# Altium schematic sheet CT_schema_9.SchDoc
size 226 x 144 mm
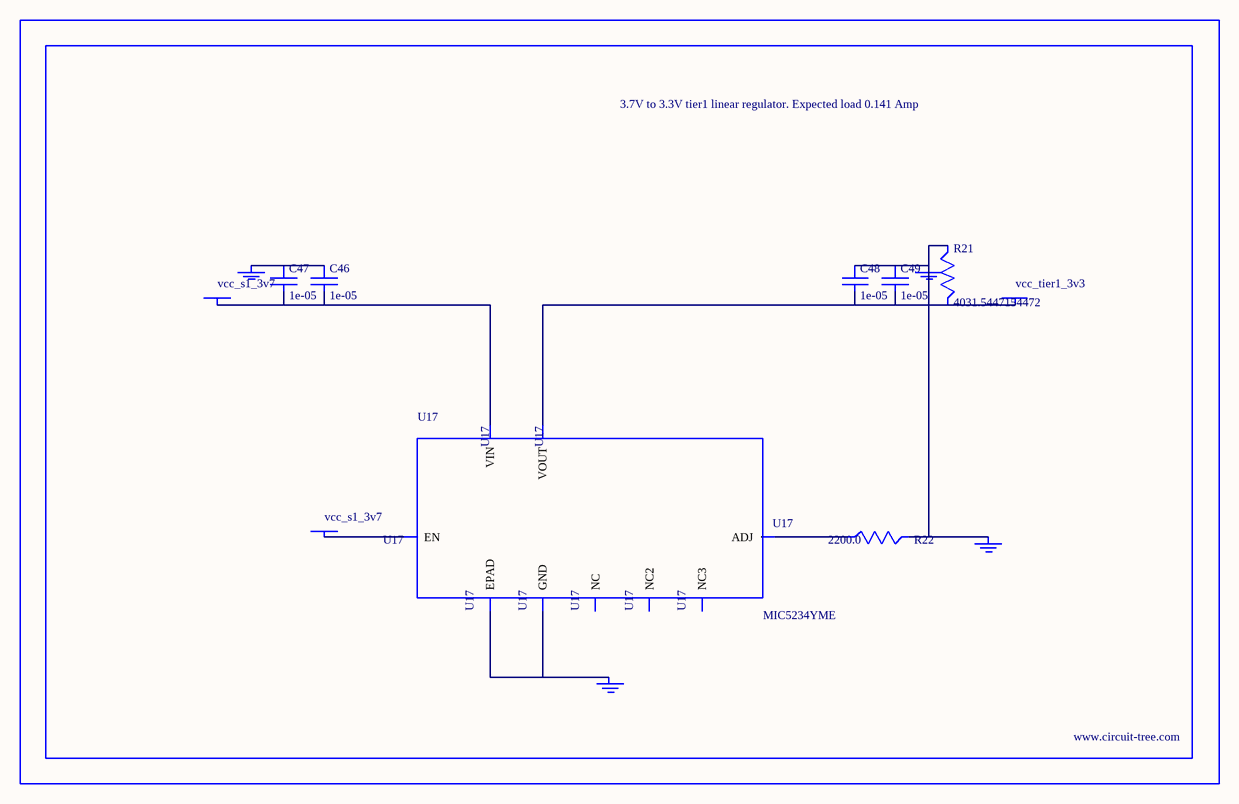
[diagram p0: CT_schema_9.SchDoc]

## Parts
BORDER8  (no value)
C46  1e-05  [C1210]
C47  1e-05  [C1210]
C48  1e-05  [C1210]
C49  1e-05  [C1210]
GND_INSTANCE_8_0  (no value)
GND_INSTANCE_8_1  (no value)
GND_INSTANCE_8_2  (no value)
GND_INSTANCE_8_3  (no value)
POWER_INSTANCE_8_0  vcc_tier1_3v3
POWER_INSTANCE_8_1  vcc_s1_3v7
POWER_INSTANCE_8_2  vcc_s1_3v7
R21  4031.5447154472  [R0603]
R22  2200.0  [R0603]
U17  MIC5234YME  [SOIC-8_EP]

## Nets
NetC46_1: C46.1 C47.1 GND_INSTANCE_8_3.0(GND)
NetC46_2: C46.2 C47.2 POWER_INSTANCE_8_2.0(PWR) U17.8(VIN)
NetC48_1: C48.1 C49.1 GND_INSTANCE_8_0.0(GND) GND_INSTANCE_8_1.0(GND) R21.1 R22.2
NetC48_2: C48.2 C49.2 POWER_INSTANCE_8_0.0(PWR) R21.2 U17.1(VOUT)
NetGND_INSTANCE_8_2_0: GND_INSTANCE_8_2.0(GND) U17.7(GND) U17.EPAD
NetPOWER_INSTANCE_8_1_0: POWER_INSTANCE_8_1.0(PWR) U17.5(EN)
NetR22_1: R22.1 U17.4(ADJ)

Not connected (* = marked no-connect by the designer): U17 2(NC) 3(NC2) 6(NC3)

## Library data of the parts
BORDER8 = BORDER_PAGE8
C46-C49 = C1210C106K5PACTU
GND_INSTANCE_8_0-GND_INSTANCE_8_3 = GND
POWER_INSTANCE_8_0-POWER_INSTANCE_8_2 = PWR
R21 = R21
R22 = RC0603JR-072K2L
